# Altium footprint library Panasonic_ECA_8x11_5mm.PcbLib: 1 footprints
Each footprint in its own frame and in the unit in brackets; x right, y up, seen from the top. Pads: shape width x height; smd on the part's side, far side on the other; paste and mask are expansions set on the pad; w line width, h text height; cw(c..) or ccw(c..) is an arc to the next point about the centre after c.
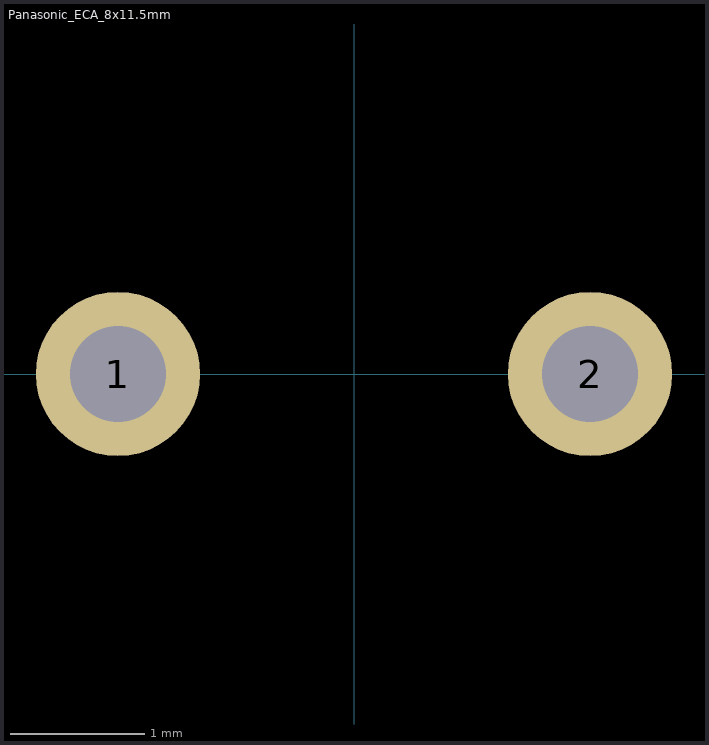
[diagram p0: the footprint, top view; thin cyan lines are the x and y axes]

## Panasonic_ECA_8x11.5mm [mil]
pads (2):
  round 48 hole 28: 1(-69,0) 2(69,0)
M5 Assembly Top:
  text ".Designator" at -99,-13 h40
3D body: height 397.48, standoff -230.03, extent -157.42,-11.8 157.55,582.76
